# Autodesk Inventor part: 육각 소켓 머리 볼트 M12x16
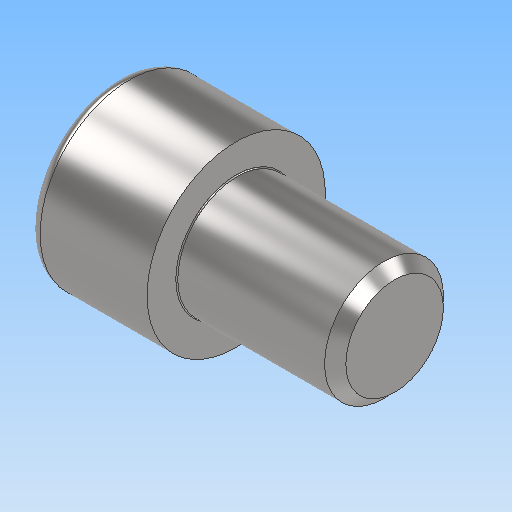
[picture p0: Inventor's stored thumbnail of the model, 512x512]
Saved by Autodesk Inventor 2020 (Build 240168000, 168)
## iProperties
Created: 2024-07
Part Number: 육각 소켓 머리 볼트 M12x16
Material: 강철, 연강
Description: 6각머리 태핑 나사
Document SubType Name: Modeling
Designer: oem
Density: 7.85 g/cm^3
Appearance: 기본값
Author: jhkim
Sending System: Autodesk Inventor 2025
Preprocessor: ST-DEVELOPER v20
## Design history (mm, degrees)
feature "Solid1"
node "솔리드1"
